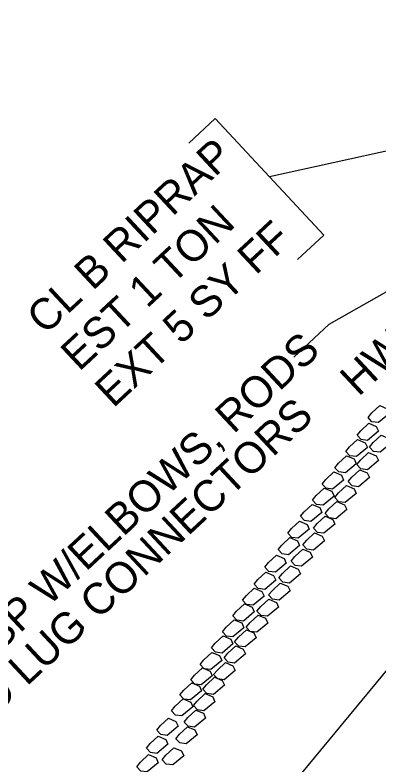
# Model space of a CAD drawing. Extents: x 2384780 to 2405432, y 547869 to 573706.
# Drawn here: x 2399474.3 to 2399532.6, y 561289.2 to 561409.4 of the extents above; entities that cross this region are included whole.
import ezdxf

# ---------------------------------------------------------------- set-up
doc = ezdxf.new("R2010")
doc.units = 0
for name, color, linetype in [('Old_Level_1', 7, 'Continuous'), ('Old_Level_20', 7, 'Continuous'), ('Old_Level_5', 7, 'Continuous'), ('Old_Level_63', 7, 'Continuous')]:
    doc.layers.add(name, color=color, linetype=linetype)

msp = doc.modelspace()

# ---------------------------------------------------------------- linework, layer by layer
at = {"layer": 'Old_Level_1'}
msp.add_line((2399551.91, 561391.59), (2399515.09, 561383.45), dxfattribs=at)
at = {"layer": 'Old_Level_20'}
for points in [[(2399502.16, 561388.87), (2399506.37, 561392.8), (2399523.8, 561374.1), (2399519.59, 561370.17)], [(2399530.86, 561344.86), (2399531.46, 561345.6), (2399532.73, 561346.79), (2399533.95, 561346.27), (2399534.3, 561345.5), (2399532.55, 561344.04), (2399531.5, 561344.17), (2399530.86, 561344.86)], [(2399529.1, 561342.01), (2399529.7, 561342.75), (2399530.97, 561343.93), (2399532.19, 561343.42), (2399532.54, 561342.65), (2399530.78, 561341.19), (2399529.74, 561341.32), (2399529.1, 561342.01)], [(2399527.32, 561339.41), (2399527.92, 561340.15), (2399529.19, 561341.34), (2399530.41, 561340.82), (2399530.76, 561340.05), (2399529.01, 561338.59), (2399527.96, 561338.73), (2399527.32, 561339.41)], [(2399531.11, 561340.11), (2399531.71, 561340.84), (2399532.98, 561342.03), (2399534.2, 561341.51), (2399534.55, 561340.74), (2399532.79, 561339.28), (2399531.75, 561339.42), (2399531.11, 561340.11)], [(2399525.54, 561336.82), (2399526.14, 561337.55), (2399527.41, 561338.74), (2399528.63, 561338.22), (2399528.98, 561337.46), (2399527.23, 561336), (2399526.18, 561336.13), (2399525.54, 561336.82)], [(2399529.09, 561337.32), (2399529.69, 561338.06), (2399530.96, 561339.25), (2399532.18, 561338.73), (2399532.53, 561337.96), (2399530.77, 561336.5), (2399529.73, 561336.63), (2399529.09, 561337.32)], [(2399527.66, 561334.58), (2399528.26, 561335.32), (2399529.53, 561336.5), (2399530.75, 561335.99), (2399531.1, 561335.22), (2399529.34, 561333.76), (2399528.3, 561333.89), (2399527.66, 561334.58)], [(2399523.51, 561334.2), (2399524.11, 561334.94), (2399525.38, 561336.13), (2399526.6, 561335.61), (2399526.95, 561334.84), (2399525.19, 561333.38), (2399524.15, 561333.52), (2399523.51, 561334.2)], [(2399525.54, 561332.04), (2399526.13, 561332.78), (2399527.41, 561333.97), (2399528.63, 561333.45), (2399528.98, 561332.68), (2399527.22, 561331.22), (2399526.18, 561331.36), (2399525.54, 561332.04)], [(2399521.99, 561331.63), (2399522.58, 561332.36), (2399523.86, 561333.55), (2399525.08, 561333.03), (2399525.42, 561332.26), (2399523.67, 561330.8), (2399522.63, 561330.94), (2399521.99, 561331.63)], [(2399520.04, 561329.02), (2399520.64, 561329.75), (2399521.91, 561330.94), (2399523.13, 561330.42), (2399523.48, 561329.65), (2399521.72, 561328.19), (2399520.68, 561328.33), (2399520.04, 561329.02)], [(2399524.01, 561329.47), (2399524.61, 561330.2), (2399525.88, 561331.39), (2399527.1, 561330.87), (2399527.45, 561330.1), (2399525.7, 561328.64), (2399524.65, 561328.78), (2399524.01, 561329.47)], [(2399522.13, 561327.12), (2399522.73, 561327.85), (2399524, 561329.04), (2399525.22, 561328.52), (2399525.57, 561327.76), (2399523.81, 561326.3), (2399522.77, 561326.43), (2399522.13, 561327.12)], [(2399518.01, 561326.32), (2399518.61, 561327.05), (2399519.88, 561328.24), (2399521.1, 561327.72), (2399521.45, 561326.96), (2399519.69, 561325.5), (2399518.65, 561325.63), (2399518.01, 561326.32)], [(2399516.46, 561323.68), (2399517.06, 561324.42), (2399518.33, 561325.6), (2399519.55, 561325.09), (2399519.9, 561324.32), (2399518.15, 561322.86), (2399517.1, 561322.99), (2399516.46, 561323.68)], [(2399520.44, 561324.44), (2399521.04, 561325.18), (2399522.31, 561326.37), (2399523.53, 561325.85), (2399523.88, 561325.08), (2399522.13, 561323.62), (2399521.08, 561323.76), (2399520.44, 561324.44)], [(2399518.53, 561321.84), (2399519.13, 561322.58), (2399520.4, 561323.76), (2399521.62, 561323.25), (2399521.97, 561322.48), (2399520.21, 561321.02), (2399519.17, 561321.15), (2399518.53, 561321.84)], [(2399514.33, 561320.87), (2399514.93, 561321.61), (2399516.21, 561322.79), (2399517.43, 561322.28), (2399517.77, 561321.51), (2399516.02, 561320.05), (2399514.98, 561320.18), (2399514.33, 561320.87)], [(2399516.59, 561319.14), (2399517.18, 561319.87), (2399518.46, 561321.06), (2399519.68, 561320.54), (2399520.03, 561319.78), (2399518.27, 561318.32), (2399517.23, 561318.45), (2399516.59, 561319.14)], [(2399512.64, 561318.14), (2399513.24, 561318.87), (2399514.51, 561320.06), (2399515.73, 561319.54), (2399516.08, 561318.77), (2399514.32, 561317.31), (2399513.28, 561317.45), (2399512.64, 561318.14)], [(2399514.94, 561316.41), (2399515.54, 561317.14), (2399516.81, 561318.33), (2399518.03, 561317.81), (2399518.38, 561317.05), (2399516.62, 561315.59), (2399515.58, 561315.72), (2399514.94, 561316.41)], [(2399510.78, 561315.58), (2399511.38, 561316.32), (2399512.65, 561317.51), (2399513.87, 561316.99), (2399514.22, 561316.22), (2399512.46, 561314.76), (2399511.42, 561314.9), (2399510.78, 561315.58)], [(2399509.22, 561313.05), (2399509.81, 561313.79), (2399511.09, 561314.98), (2399512.31, 561314.46), (2399512.65, 561313.69), (2399510.9, 561312.23), (2399509.86, 561312.37), (2399509.22, 561313.05)], [(2399513.08, 561313.81), (2399513.68, 561314.55), (2399514.96, 561315.73), (2399516.18, 561315.22), (2399516.52, 561314.45), (2399514.77, 561312.99), (2399513.73, 561313.12), (2399513.08, 561313.81)], [(2399507.55, 561310.52), (2399508.15, 561311.25), (2399509.42, 561312.44), (2399510.64, 561311.92), (2399510.99, 561311.15), (2399509.24, 561309.69), (2399508.19, 561309.83), (2399507.55, 561310.52)], [(2399511.37, 561311.27), (2399511.97, 561312), (2399513.25, 561313.19), (2399514.47, 561312.67), (2399514.81, 561311.91), (2399513.06, 561310.45), (2399512.01, 561310.58), (2399511.37, 561311.27)], [(2399505.8, 561307.92), (2399506.4, 561308.66), (2399507.67, 561309.85), (2399508.89, 561309.33), (2399509.24, 561308.56), (2399507.48, 561307.1), (2399506.44, 561307.24), (2399505.8, 561307.92)], [(2399509.5, 561308.91), (2399510.1, 561309.65), (2399511.38, 561310.83), (2399512.6, 561310.32), (2399512.94, 561309.55), (2399511.19, 561308.09), (2399510.15, 561308.22), (2399509.5, 561308.91)], [(2399507.8, 561306.32), (2399508.4, 561307.06), (2399509.67, 561308.24), (2399510.89, 561307.73), (2399511.24, 561306.96), (2399509.48, 561305.5), (2399508.44, 561305.63), (2399507.8, 561306.32)], [(2399504, 561305.28), (2399504.59, 561306.02), (2399505.87, 561307.2), (2399507.09, 561306.69), (2399507.44, 561305.92), (2399505.68, 561304.46), (2399504.64, 561304.59), (2399504, 561305.28)], [(2399506.14, 561303.64), (2399506.74, 561304.38), (2399508.02, 561305.56), (2399509.24, 561305.05), (2399509.58, 561304.28), (2399507.83, 561302.82), (2399506.79, 561302.95), (2399506.14, 561303.64)], [(2399502.47, 561302.8), (2399503.07, 561303.54), (2399504.35, 561304.72), (2399505.57, 561304.21), (2399505.91, 561303.44), (2399504.16, 561301.98), (2399503.12, 561302.11), (2399502.47, 561302.8)], [(2399504.42, 561301.29), (2399505.02, 561302.03), (2399506.29, 561303.21), (2399507.51, 561302.7), (2399507.86, 561301.93), (2399506.1, 561300.47), (2399505.06, 561300.6), (2399504.42, 561301.29)], [(2399500.75, 561300.4), (2399501.35, 561301.14), (2399502.63, 561302.33), (2399503.85, 561301.81), (2399504.19, 561301.04), (2399502.44, 561299.58), (2399501.39, 561299.72), (2399500.75, 561300.4)], [(2399502.91, 561298.67), (2399503.51, 561299.4), (2399504.78, 561300.59), (2399506, 561300.07), (2399506.35, 561299.3), (2399504.59, 561297.84), (2399503.55, 561297.98), (2399502.91, 561298.67)], [(2399499.38, 561297.83), (2399499.98, 561298.57), (2399501.25, 561299.75), (2399502.47, 561299.24), (2399502.82, 561298.47), (2399501.06, 561297.01), (2399500.02, 561297.14), (2399499.38, 561297.83)], [(2399501.4, 561296.04), (2399502, 561296.78), (2399503.27, 561297.97), (2399504.49, 561297.45), (2399504.84, 561296.68), (2399503.08, 561295.22), (2399502.04, 561295.36), (2399501.4, 561296.04)], [(2399497.02, 561294.72), (2399497.62, 561295.46), (2399498.89, 561296.64), (2399500.11, 561296.13), (2399500.46, 561295.36), (2399498.7, 561293.9), (2399497.66, 561294.03), (2399497.02, 561294.72)], [(2399500.06, 561293.37), (2399500.66, 561294.1), (2399501.93, 561295.29), (2399503.15, 561294.77), (2399503.5, 561294.01), (2399501.74, 561292.55), (2399500.7, 561292.68), (2399500.06, 561293.37)], [(2399495.38, 561291.84), (2399495.98, 561292.58), (2399497.25, 561293.77), (2399498.47, 561293.25), (2399498.82, 561292.48), (2399497.06, 561291.02), (2399496.02, 561291.16), (2399495.38, 561291.84)], [(2399497.9, 561289.99), (2399498.5, 561290.73), (2399499.77, 561291.92), (2399500.99, 561291.4), (2399501.34, 561290.63), (2399499.58, 561289.17), (2399498.54, 561289.31), (2399497.9, 561289.99)], [(2399493.84, 561288.88), (2399494.44, 561289.62), (2399495.71, 561290.81), (2399496.93, 561290.29), (2399497.28, 561289.52), (2399495.52, 561288.06), (2399494.48, 561288.19), (2399493.84, 561288.88)]]:
    msp.add_lwpolyline(points, dxfattribs=at)
at = {"layer": 'Old_Level_5'}
for p, q in [((2399524.65, 561359.82), (2399562.59, 561381.43)), ((2399584.85, 561366.13), (2399515.08, 561281.64)), ((2399518.99, 561354.54), (2399524.65, 561359.82))]:
    msp.add_line(p, q, dxfattribs=at)
at = {"layer": 'Old_Level_63'}
msp.add_circle((2399645.61, 561347.28), 187.94, dxfattribs=at)

# ---------------------------------------------------------------- texts
at = {"layer": 'Old_Level_1'}
for s, p in [('CL B RIPRAP', (2399479.15, 561357.98)), ('EST 1 TON', (2399484.6, 561352.13)), ('EXT 5 SY FF', (2399490.06, 561346.28))]:
    msp.add_text(s, height=5, rotation=43, dxfattribs=at).set_placement(p)
at = {"layer": 'Old_Level_5'}
for s, p in [('HW', (2399529.33, 561348.1)), ('15" CSP W/ELBOWS, RODS', (2399459.76, 561295.9)), ('AND LUG CONNECTORS', (2399464.53, 561290.79))]:
    msp.add_text(s, height=5, rotation=43, dxfattribs=at).set_placement(p)

doc.saveas('drawing.dxf')
